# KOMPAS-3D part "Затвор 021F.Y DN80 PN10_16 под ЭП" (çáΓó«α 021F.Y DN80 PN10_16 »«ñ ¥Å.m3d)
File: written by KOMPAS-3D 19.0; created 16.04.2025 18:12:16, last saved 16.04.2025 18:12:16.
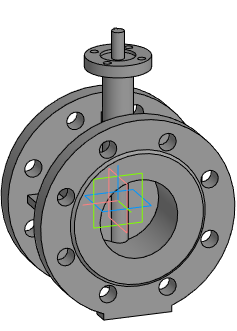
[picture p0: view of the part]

Document properties: Автор: Евгений; Полное имя файла: E:\Dendor Работа Сачек\3D для проекитирвщиков\1.6 Тип 021F.Y Затвор дисковый поворотный фланцевый\stp_Тип 021F.Y Затвор  DN40 PN10_16 под ЭП\Затвор 021F.Y DN80 PN10_16 под ЭП.m3d

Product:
- Part/product: Затвор 021F.Y DN80 PN10_16 под ЭП

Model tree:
1. Операция без истории:1  (labels: Затвор 021F.Y DN80 PN10_16 под ЭП)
